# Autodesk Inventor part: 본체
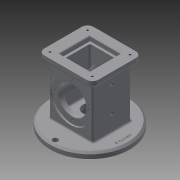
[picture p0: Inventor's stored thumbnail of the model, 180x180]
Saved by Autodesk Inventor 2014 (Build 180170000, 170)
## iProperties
Created: 2019-08
Part Number: 본체
Material: 일반
Document SubType Name: Modeling
Designer: NET
Density: 1 g/cm^3
Appearance: 기본값
Author: NET
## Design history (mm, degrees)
sketch "스케치1"
  geometry: C1 r 67.5 at (0, 0); 1 further point
  constraints: 1 centre point, 1 coincident
  dimensions: "d0" = 135 diameter of C1
extrude "돌출1" new body sketch "스케치1" distance "d1" = 10; taper "d2" = 0 deg
chamfer "모따기1" distance "d3" = 3; stored, may be unused: second distance "d4" = 2, angle "d5" = 45 deg
sketch "스케치2"
  geometry: L1 (-37, 33)-(37, 33); L2 (37, 33)-(37, -33); L3 (37, -33)-(-37, -33); L4 (-37, -33)-(-37, 33); L5 (0, 0)-(28.125, 0); L6 (0, 0)-(0, 30); C1 r 64.5 at (0, 0) reference
  constraints: 12 end point, 3 perpendicular, 2 parallel, 1 horizontal
  dimensions: "d6" = 74 distance between parallel lines of L2 L4; "d7" = 66 distance between parallel lines of L3 L1; "d8" = 37 distance between parallel lines of L4 L6; "d9" = 33 distance between parallel lines of L5 L1
extrude "돌출2" join sketch "스케치2" distance "d10" = 88; taper "d11" = 0 deg
sketch "스케치3"
  geometry: L1 (-46, 42)-(46, 42); L2 (46, 42)-(46, -42); L3 (46, -42)-(-46, -42); L4 (-46, -42)-(-46, 42); L5 (0, 0)-(0, 5.099); L6 (0, 0)-(7.648, 0)
  constraints: 12 end point, 3 parallel, 2 perpendicular, 1 horizontal
  dimensions: "d12" = 46 distance between parallel lines of L4 L5; "d13" = 92 distance between parallel lines of L2 L4; "d14" = 42 distance between parallel lines of L6 L1; "d15" = 42 distance between parallel lines of L3 L6
extrude "돌출3" join sketch "스케치3" distance "d16" = 10; taper "d17" = 0 deg
sketch "스케치4"
  geometry: L1 (74, 0)-(0, 0) reference; L2 (0, 0)-(0, 88) reference; L3 (17.587, 44)-(37, 44); L4 (-30.5, -10)-(104.5, -10) reference; L5 (37, 0)-(37, 44); C1 r 35 at (37, 44); 1 further point
  constraints: 4 end point, 2 perpendicular, 1 centre point, 1 coincident, 1 midpoint
  dimensions: "d18" = 54 distance between parallel lines of L4 L3; "d19" = 70 diameter of C1
extrude "돌출4" cut sketch "스케치4" distance "d20" = 3; taper "d21" = 0 deg
sketch "스케치5"
  geometry: C1 r 35 at (0, 0) reference; C2 r 24 at (0, 0); 1 further point
  constraints: 1 centre point, 1 coincident
  dimensions: "d22" = 48 diameter of C2
extrude "돌출5" cut sketch "스케치5" distance "d23" = 40; taper "d24" = 0 deg
sketch "스케치6"
  geometry: L1 (0, 0)-(29, 0); L2 (0, 0)-(0, 29); L3 (0, 0)-(0, -29); L4 (0, 0)-(-29, 0); C1 r 35 at (0, 0) reference; A1 r 29 centre (0, 0) between (0, 29) and (29, 0); 1 further point
  constraints: 8 end point, 4 point on circle, 2 perpendicular, 1 centre point, 1 coincident, 1 collinear, 1 horizontal
  dimensions: "d25" = 58 diameter of A1
hole "구멍1" sketch "스케치6" at (0, 29), (-29, 0), (0, -29), (29, 0) diameter "d26" = 3.242; stored, may be unused: countersink angle "d30" = 90 deg, drill point angle "d32" = 118 deg; dims "d27" = 4, "d28" = 4, "d29" = 2, "d31" = 6
sketch "스케치7"
  geometry: L1 (-37, 33)-(37, 33) reference; L2 (0, 0)-(-59, 0); L3 (0, 0)-(0, 59); L4 (0, 0)-(0, -59); C1 r 64.5 at (0, 0) reference; C2 r 4.5 at (0, 59); C3 r 4.5 at (-59, 0); C4 r 4.5 at (0, -59); A1 r 59 centre (0, 0) between (-59, 0) and (0, 59)
  constraints: 6 end point, 4 centre point, 4 coincident, 3 point on circle, 1 collinear, 1 parallel, 1 perpendicular
  dimensions: "d33" = 118 diameter of A1; "d34" = 9 diameter of C2; "d35" = 9 diameter of C3; "d36" = 9 diameter of C4
extrude "돌출6" cut sketch "스케치7" distance "d37" = 10; taper "d38" = 0 deg
sketch "스케치8"
  geometry: L1 (-26, 26)-(26, 26); L2 (26, 26)-(26, -26); L3 (26, -26)-(-26, -26); L4 (-26, -26)-(-26, 26); L5 (0, 0)-(13.11, 0); L6 (0, 0)-(0, 8.068)
  constraints: 12 end point, 3 perpendicular, 2 parallel, 1 horizontal
  dimensions: "d39" = 52 distance of L2.end L3.end; "d40" = 52 distance of L1.end L2.end; "d41" = 26 distance between parallel lines of L5 L1; "d42" = 26 distance between parallel lines of L4 L6
extrude "돌출7" cut sketch "스케치8" distance "d43" = 8; taper "d44" = 0 deg
sketch "스케치9"
  geometry: L1 (-22, 22)-(22, 22); L2 (22, 22)-(22, -22); L3 (22, -22)-(-22, -22); L4 (-22, -22)-(-22, 22); 1 further point
  constraints: 8 end point, 2 parallel, 1 horizontal, 1 perpendicular
  dimensions: "d45" = 44 distance of L2.end L3.end; "d46" = 44 distance of L1.end L2.end; "d47" = 22 distance from line of point (0, 0) L4; "d48" = 22 distance from line of point (0, 0) L1
extrude "돌출8" cut sketch "스케치9" distance "d49" = 74; taper "d50" = 0 deg
sketch "스케치10"
  geometry: C1 r 67.5 at (0, 0) reference; C2 r 25 at (0, 0)
  constraints: 1 centre point, 1 coincident
  dimensions: "d51" = 50 diameter of C2
extrude "돌출9" cut sketch "스케치10" distance "d52" = 18; taper "d53" = 0 deg
sketch "스케치11"
  geometry: C1 r 25 at (0, 0) reference; C2 r 12.5 at (0, 0)
  constraints: 1 centre point, 1 coincident
  dimensions: "d54" = 25 diameter of C2
extrude "돌출10" cut sketch "스케치11" distance "d55" = 10; taper "d56" = 0 deg
fillet "모깎기1" dims "d57" = 10
node "작업 평면1"
sketch "스케치12"
  geometry: L1 (66, 0)-(0, 0) reference; L2 (0, 88)-(66, 88) reference; L3 (33, 88)-(33, 0); L4 (21.383, 27)-(33, 27); L5 (33, 70)-(45.968, 70); L6 (58, -10)-(8, -10) reference; C1 r 10.58 at (33, 27); C2 r 4.827 at (33, 70); 1 further point
  constraints: 6 end point, 2 centre point, 2 coincident, 2 midpoint, 2 point on line, 1 parallel, 1 perpendicular
  dimensions: "d59" = 37 distance between parallel lines of L6 L4; "d60" = 43 distance between parallel lines of L4 L5; "d61" = 9.65468 diameter of C2; "d62" = 21.16088 diameter of C1
hole "구멍2" sketch "스케치12" at (33, 70), (33, 27) diameter "d63" = 4.917; stored, may be unused: countersink angle "d67" = 90 deg, drill point angle "d69" = 118 deg; dims "d64" = 16, "d65" = 4, "d66" = 2, "d68" = 16
fillet "모깎기2" dims "d70" = 3
chamfer "모따기2" distance "d71" = 1; stored, may be unused: second distance "d72" = 2, angle "d73" = 45 deg
fillet "모깎기3" dims "d74" = 3
fillet "모깎기4" dims "d75" = 3
fillet "모깎기5" dims "d76" = 3
fillet "모깎기6" dims "d77" = 3
fillet "모깎기7" dims "d78" = 3
sketch "스케치13"
  geometry: A1 r 10 centre (-36, 32) between (-36, 42) and (-46, 32) reference; A2 r 10 centre (-36, -32) between (-46, -32) and (-36, -42) reference; A3 r 10 centre (36, -32) between (36, -42) and (46, -32) reference; A4 r 10 centre (36, 32) between (46, 32) and (36, 42) reference; 1 further point
hole "구멍3" sketch "스케치13" at (-36, 32), (-36, -32), (36, 32), (36, -32) diameter "d79" = 3.242; stored, may be unused: countersink angle "d83" = 90 deg, drill point angle "d85" = 118 deg; dims "d80" = 4, "d81" = 4, "d82" = 2, "d84" = 6
sketch "스케치14"
  geometry: C1 r 64.5 at (0, 0) reference; C2 r 4.5 at (0, 59) reference; 1 further point
  constraints: 1 coincident, 1 vertical alignment, 2 other
feature "엠보싱1" sketch "스케치14" dims "d2" = 0, "d12" = 46, "d13" = 92, "d14" = 42, "d15" = 42, "d86" = 0.5, "d87" = 0
node "솔리드1"
mirror "대칭1"
